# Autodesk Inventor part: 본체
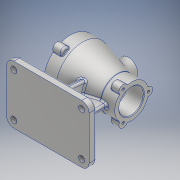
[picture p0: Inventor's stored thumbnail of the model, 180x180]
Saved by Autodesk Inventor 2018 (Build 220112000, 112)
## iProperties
Created: 2020-03
Part Number: 본체
Material: 알루미늄 6061
Document SubType Name: Modeling
Designer: Administrator
Density: 2.7 g/cm^3
Appearance: 알루미늄 - 평지
Mass: 1000.42 g
Surface Area: 865.263 cm^2
Volume: 370.527 cm^3
Author: Administrator
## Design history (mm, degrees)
sketch "스케치1"
  geometry: L1 (67.5, -47.5)-(-67.5, -47.5); L2 (-67.5, -47.5)-(-67.5, 47.5); L3 (-67.5, 47.5)-(67.5, 47.5); L4 (67.5, 47.5)-(67.5, -47.5); L5 (67.5, -47.5)-(-67.5, 47.5); L6 (-67.5, -47.5)-(67.5, 47.5); 1 further point
  constraints: 12 end point, 2 midpoint, 2 parallel, 1 horizontal, 1 perpendicular
  dimensions: "d0" = 135 distance of L1.start L1.end; "d1" = 95 distance of L1.end L2.end
extrude "돌출1" new body sketch "스케치1" distance "d2" = 12; taper "d3" = 0 deg
fillet "모깎기1" dims "d4" = 12
sketch "스케치2"
  geometry: A1 r 12 centre (-55.5, 35.5) between (-55.5, 47.5) and (-67.5, 35.5) reference; A2 r 12 centre (-55.5, -35.5) between (-67.5, -35.5) and (-55.5, -47.5) reference; A3 r 12 centre (55.5, -35.5) between (55.5, -47.5) and (67.5, -35.5) reference; A4 r 12 centre (55.5, 35.5) between (67.5, 35.5) and (55.5, 47.5) reference; 5 further points
  constraints: 4 coincident
hole "구멍1" sketch "스케치2" at (-55.5, 35.5), (-55.5, -35.5), (55.5, -35.5), (55.5, 35.5) diameter "d5" = 10; stored, may be unused: countersink angle "d9" = 90 deg, drill point angle "d11" = 118 deg; dims "d6" = 6, "d7" = 4, "d8" = 2, "d10" = 8
sketch "스케치3"
  geometry: L1 (0, 0)-(0, 87); L2 (-50, 87)-(50, 87); L3 (-50, 87)-(-50, 105.183); L4 (-50, 105.183)-(-50, 131); L5 (-50, 131)-(-30, 131); L6 (-30, 131)-(27, 114.5); L7 (27, 114.5)-(50, 114.5); L8 (50, 114.5)-(50, 87)
  constraints: 16 end point, 2 perpendicular, 1 horizontal, 1 midpoint, 1 parallel, 1 point on line, 1 vertical
  dimensions: "d12" = 87 distance of L1.end L1.start; "d13" = 100 distance of L2.start L2.end; "d14" = 88 diameter of L5 L2; "d15" = 55 diameter of L7 L2; "d16" = 20 distance from line of L5.end L4; "d17" = 77 distance from line of L6.end L4
revolve "회전1" sketch "스케치3" stored, may be unused: angle "d18" = 90 deg
sketch "스케치4"
  geometry: C1 r 7 at (0, 44); 2 further points
  constraints: 1 centre point, 1 vertical alignment, 1 other
  dimensions: "d19" = 14 diameter of C1
extrude "돌출2" join sketch "스케치4" distance "d20" = 15; taper "d21" = 0 deg
fillet "모깎기2" dims "d22" = 3
fillet "모깎기3" dims "d23" = 1
sketch "스케치5"
  geometry: A1 r 7 centre (0, 0) between (6.996, 0.249) and (-6.996, 0.249) reference; A2 r 7 centre (-38.105, -66) between (-41.818, -60.066) and (-34.823, -72.183) reference; A3 r 7 centre (38.105, -66) between (34.823, -72.183) and (41.818, -60.066) reference; 4 further points
  constraints: 3 coincident
hole "구멍2" sketch "스케치5" at (0, 0), (-38.105, -66), (38.105, -66) diameter "d27" = 4.134; stored, may be unused: countersink angle "d31" = 90 deg, drill point angle "d33" = 118 deg; dims "d28" = 9, "d29" = 4, "d30" = 2, "d32" = 11
sketch "스케치6"
  geometry: C1 r 27.5 at (0, 0) reference; C2 r 7 at (0, 27.5); 2 further points
  constraints: 1 centre point, 1 vertical alignment, 1 other
  dimensions: "d34" = 14 diameter of C2
extrude "돌출3" join sketch "스케치6" distance "d35" = 15; taper "d36" = 0 deg
fillet "모깎기4" dims "d37" = 3
fillet "모깎기5" dims "d38" = 1
sketch "스케치7"
  geometry: A1 r 4 centre (0, 0) between (3.933, 0.727) and (-3.933, 0.727) reference; A2 r 7 centre (-23.816, -41.25) between (-27.205, -35.125) and (-20.206, -47.248) reference; A3 r 7 centre (23.816, -41.25) between (20.206, -47.248) and (27.205, -35.125) reference; 4 further points
  constraints: 3 coincident
hole "구멍3" sketch "스케치7" at (0, 0), (-23.816, -41.25), (23.816, -41.25) diameter "d42" = 4.134; stored, may be unused: countersink angle "d46" = 90 deg, drill point angle "d48" = 118 deg; dims "d43" = 9, "d44" = 4, "d45" = 2, "d47" = 11
node "작업 평면1"
sketch "스케치8"
  geometry: C1 r 15 at (0, 0); 1 further point
  constraints: 1 centre point, 1 coincident
  dimensions: "d50" = 30 diameter of C1
extrude "돌출4" join sketch "스케치8" stored distance "d51" = 15; taper "d52" = 0 deg
sketch "스케치9"
  geometry: L1 (0, 0)-(0, 87); L2 (-50, 87)-(50, 87); L3 (-50, 87)-(-27, 87); L4 (-27, 87)-(-27, 123); L5 (-27, 123)-(-50, 123); L6 (-50, 123)-(-50, 87); L7 (-27, 87)-(20, 87); L8 (20, 87)-(20, 113); L9 (20, 113)-(-27, 113); L10 (-27, 113)-(-27, 87); L11 (50, 80.487)-(50, 113.395) reference; L12 (20, 87)-(50, 87); L13 (50, 87)-(50, 107); L14 (50, 107)-(20, 107); L15 (20, 107)-(20, 87)
  constraints: 28 end point, 6 parallel, 4 horizontal, 3 perpendicular, 1 midpoint, 1 point on line, 1 vertical
  dimensions: "d53" = 87 distance of L1.end L1.start; "d54" = 100 distance of L2.start L2.end; "d55" = 23 distance of L4.end L5.end; "d56" = 47 distance of L8.end L9.end; "d58" = 72 diameter of L5 L2; "d59" = 40 diameter of L14 L2; "d60" = 52 diameter of L9 L2
revolve "회전2" sketch "스케치9" stored, may be unused: angle "d61" = 90 deg
fillet "모깎기6" dims "d62" = 1
sketch "스케치10"
  geometry: C1 r 10 at (0, 0); 1 further point
  constraints: 1 centre point, 1 coincident
  dimensions: "d63" = 20 diameter of C1
extrude "돌출5" cut sketch "스케치10" stored distance "d64" = 15; taper "d65" = 0 deg
chamfer "모따기1" distance "d66" = 1; stored, may be unused: second distance "d67" = 2, angle "d68" = 45 deg
sketch "스케치12"
  geometry: L1 (12, 35.5)-(12, -35.5) reference; L2 (70.27, 19.902)-(12, 25); L3 (70.27, -19.902)-(12, -25); C1 r 26 at (87, 0) reference; A1 r 26 centre (87, 0) between (70.27, 19.902) and (70.27, -19.902); 2 further points
  constraints: 4 end point, 2 point on circle, 2 point on line, 1 centre point, 1 coincident
  dimensions: "d79" = 25 vertical distance of point (0, 0) L2.end; "d80" = 25 vertical distance of point (0, 0) L3.end; "d81" = 95 deg angle of L1 L3; "d82" = 95 deg angle of L1 L2
extrude "돌출6" join sketch "스케치12" stored distance "d83" = 8; taper "d84" = 0 deg
fillet "모깎기7" dims "d85" = 3
sketch "스케치13"
  geometry: L1 (-37, 46.144)-(-37, 8.115); L2 (37, 61.876)-(37, 8.115); L3 (55.5, 12)-(-55.5, 12) reference; L4 (-37, 8.115)-(-26.771, 8.115); L5 (-26.771, 8.115)-(37, 8.115); L6 (-25.641, 50.307)-(15.958, 58.823); L7 (15.958, 58.823)-(32.438, 63.131); L8 (32.438, 63.131)-(37, 63.131); L9 (37, 63.131)-(37, 61.876); L10 (67.5, 12)-(67.5, 0) reference; A1 r 17.577 centre (-37, 63.72) between (-37, 46.144) and (-25.641, 50.307); 1 further point
  constraints: 16 end point, 2 perpendicular, 2 point on circle, 2 point on line, 1 centre point, 1 collinear, 1 horizontal, 1 vertical
  dimensions: "d86" = 37 distance from line of L2 point (0, 0); "d87" = 37 distance from line of point (0, 0) L1
extrude "돌출7" join sketch "스케치13" stored distance "d88" = 8; taper "d89" = 0 deg
fillet "모깎기8" dims "d90" = 3
fillet "모깎기9" dims "d91" = 3
fillet "모깎기10" dims "d92" = 3
fillet "모깎기11" dims "d93" = 3
fillet "모깎기12" dims "d94" = 3
fillet "모깎기13" dims "d95" = 3
fillet "모깎기14" dims "d96" = 3
fillet "모깎기15" dims "d97" = 3
fillet "모깎기16" dims "d98" = 3
chamfer "모따기2" distance "d99" = 1; stored, may be unused: second distance "d100" = 2, angle "d101" = 45 deg
chamfer "모따기3" distance "d102" = 1; stored, may be unused: second distance "d103" = 2, angle "d104" = 45 deg
fillet "모깎기17" dims "d105" = 3
fillet "모깎기18" dims "d106" = 3
fillet "모깎기19" dims "d107" = 3
fillet "모깎기20" dims "d108" = 3
sketch "스케치14"
  geometry: L1 (-55.5, -47.5)-(55.5, -47.5) reference; 2 further points
  constraints: 1 vertical alignment, 1 other
  dimensions: "d109" = 10 distance from line of L1 point (0, -37.5)
feature "엠보싱1" sketch "스케치14" dims "d110" = 0.5, "d111" = 0
node "솔리드1"
pattern_circular "원형 패턴1" dims angle "d25" = 360 deg
pattern_circular "원형 패턴2" dims angle "d40" = 360 deg
node "투영된 루프1"
other parameters: "d49" = 132
